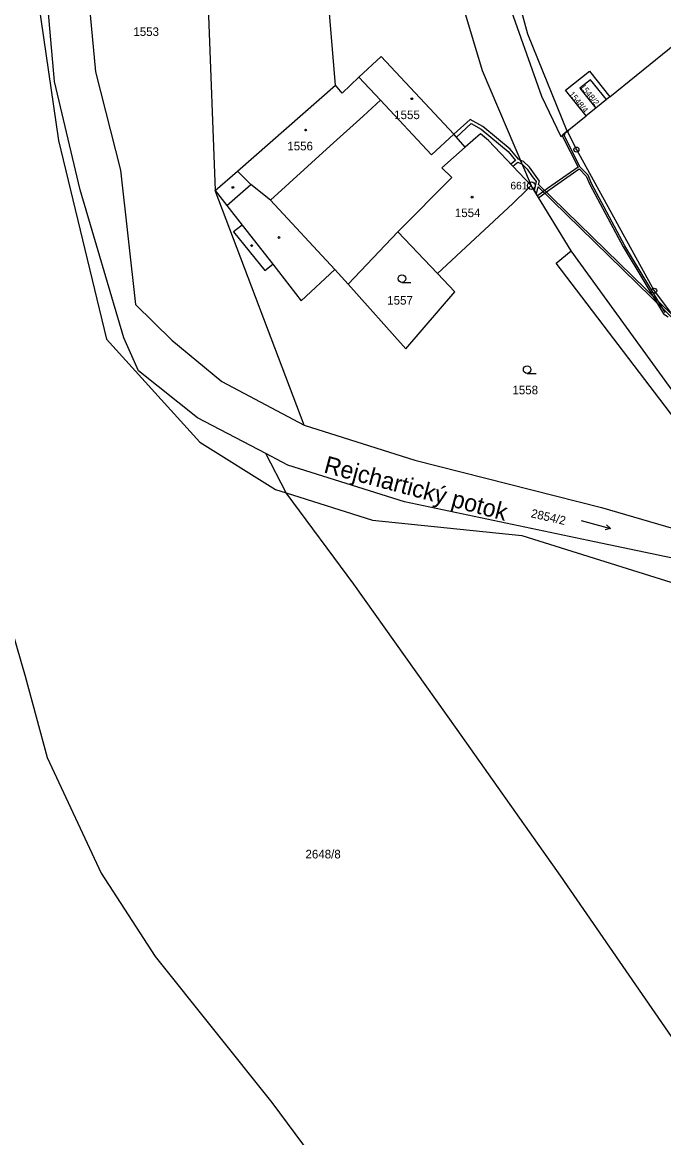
# Model space of a CAD drawing. Extents: x -562167 to -556918, y -1077891 to -1070763.
# Drawn here: x -560295.1 to -560168.6, y -1075431.3 to -1075211 of the extents above; entities that cross this region are included whole.
import ezdxf

# ---------------------------------------------------------------- set-up
doc = ezdxf.new("R2010")
doc.units = 0
for name, color, linetype in [('Hranice parcel', 7, 'Continuous'), ('Parcelní čísla', 7, 'Continuous'), ('Pop  PČ popisy', 7, 'Continuous'), ('Vnitřní kresba', 7, 'Continuous'), ('Věcná břemena k části', 7, 'Continuous'), ('Značky bodu BP', 7, 'Continuous'), ('Značky budov', 7, 'Continuous'), ('Značky kultur', 7, 'Continuous')]:
    doc.layers.add(name, color=color, linetype=linetype)

msp = doc.modelspace()

# ---------------------------------------------------------------- linework, layer by layer
at = {"layer": 'Hranice parcel'}
for p, q in [((-560195.41, -1075213.39), (-560213.2, -1075148.43)), ((-560233.39, -1075223.45), (-560237.46, -1075173.67)), ((-560258.5, -1075208.05), (-560257.08, -1075244.24)), ((-560179.25, -1075225.71), (-560156.69, -1075207.44)), ((-560187.64, -1075232.51), (-560195.41, -1075213.39)), ((-560252.69, -1075240.39), (-560233.39, -1075223.45)), ((-560228.76, -1075221.87), (-560224.48, -1075226.43)), ((-560179.91, -1075226.25), (-560182.01, -1075227.95)), ((-560179.25, -1075225.71), (-560179.91, -1075226.25)), ((-560187.64, -1075232.51), (-560183.9, -1075229.48)), ((-560182.01, -1075227.95), (-560183.9, -1075229.48)), ((-560187.64, -1075232.51), (-560185.83, -1075236.16)), ((-560257.08, -1075244.24), (-560252.69, -1075240.39)), ((-560186.88, -1075256.18), (-560194.75, -1075243.27)), ((-560239.53, -1075290.55), (-560257.08, -1075244.24)), ((-560253.48, -1075252.39), (-560247.3, -1075260.02)), ((-560247.12, -1075296.18), (-560260.61, -1075289.1)), ((-560243.08, -1075303.96), (-560247.12, -1075296.18)), ((-560242.79, -1075298.45), (-560247.12, -1075296.18))]:
    msp.add_line(p, q, dxfattribs=at)
for points in [[(-560468.72, -1074981.28), (-560446.94, -1075005.24), (-560438.95, -1075016.91), (-560425.77, -1075038.67), (-560409.04, -1075068.96), (-560398.41, -1075088.55), (-560384.84, -1075113.41), (-560359.86, -1075158.18), (-560352.19, -1075171.57), (-560344.85, -1075189.04), (-560335.77, -1075208.9), (-560321.29, -1075251.14), (-560313.71, -1075276.41), (-560308.43, -1075290.81), (-560301.52, -1075316.46), (-560294.61, -1075340.14), (-560290.27, -1075356.18), (-560279.56, -1075379.07), (-560268.94, -1075395.49), (-560245.91, -1075424.32), (-560221.55, -1075457.21), (-560206.93, -1075476.56), (-560193.15, -1075492.44), (-560170.99, -1075515.93)], [(-560377.5, -1075001.63), (-560371.77, -1075022.43), (-560361.38, -1075042.53), (-560353.72, -1075060.11), (-560342.27, -1075079.82), (-560325.5, -1075114.4), (-560301.62, -1075166.88), (-560296.28, -1075178.83), (-560291.97, -1075207.26), (-560288.04, -1075234.38), (-560278.55, -1075273.6), (-560260.14, -1075293.96), (-560245.2, -1075303.29), (-560243.08, -1075303.96)], [(-560213.2, -1075148.43), (-560209.41, -1075171.84), (-560199.73, -1075205.64), (-560192.7, -1075225.61)], [(-560284.98, -1075174.75), (-560283.71, -1075188.4), (-560280.69, -1075220.82), (-560275.79, -1075240.25), (-560272.84, -1075266.73), (-560265.66, -1075273.78), (-560255.76, -1075281.97), (-560239.53, -1075290.55)], [(-560260.61, -1075289.1), (-560272.24, -1075279.86), (-560275.15, -1075273.34), (-560283.73, -1075244.13), (-560288.79, -1075222.69), (-560292.95, -1075175.49)], [(-560215.2, -1075184.5), (-560204.42, -1075220.53), (-560194.75, -1075243.27)], [(-560210.04, -1075233.08), (-560224.35, -1075217.75), (-560228.76, -1075221.87)], [(-560183.9, -1075229.48), (-560187.96, -1075224.44), (-560183.23, -1075220.68), (-560179.25, -1075225.71)], [(-560228.76, -1075221.87), (-560232.04, -1075224.99), (-560233.39, -1075223.45)], [(-560179.91, -1075226.25), (-560183.06, -1075222.36), (-560185.16, -1075224.06), (-560182.01, -1075227.95)], [(-560192.7, -1075225.61), (-560188.93, -1075233.56), (-560187.64, -1075232.51)], [(-560224.48, -1075226.43), (-560227.9, -1075229.54), (-560234.39, -1075235.43), (-560246.19, -1075246.15)], [(-560210.04, -1075233.08), (-560214.42, -1075237.16), (-560224.48, -1075226.43)], [(-560194.75, -1075243.27), (-560203.15, -1075234.38), (-560204.74, -1075233.03), (-560207.76, -1075235.7), (-560210.04, -1075233.08)], [(-560185.83, -1075236.16), (-560170.49, -1075264.02), (-560167.24, -1075268.32)], [(-560246.19, -1075246.15), (-560250.07, -1075243.04), (-560252.69, -1075240.39)], [(-560213.26, -1075260.63), (-560198.37, -1075246.77), (-560195.48, -1075243.98), (-560194.75, -1075243.27)], [(-560257.08, -1075244.24), (-560254.79, -1075247.19), (-560251.77, -1075251.05), (-560253.48, -1075252.39)], [(-560230.88, -1075262.76), (-560221.04, -1075252.4), (-560213.26, -1075260.63)], [(-560142.4, -1075321.68), (-560151.85, -1075308.44), (-560189.85, -1075258.59), (-560186.88, -1075256.18)], [(-560131.73, -1075330.69), (-560140.28, -1075319.37), (-560149.99, -1075307.09), (-560186.88, -1075256.18)], [(-560247.3, -1075260.02), (-560245.73, -1075258.79), (-560240.11, -1075266)], [(-560240.11, -1075266), (-560233.49, -1075259.85), (-560230.88, -1075262.76)], [(-560230.88, -1075262.76), (-560219.49, -1075275.51), (-560209.84, -1075264.25), (-560213.26, -1075260.63)], [(-560239.53, -1075290.55), (-560217.71, -1075297.51), (-560180.89, -1075306.83), (-560163.49, -1075311.91), (-560151.81, -1075316.39), (-560142.4, -1075321.68)], [(-560045.55, -1075464.21), (-560067.84, -1075432.85), (-560097.73, -1075390.37), (-560116.01, -1075366.17), (-560124.2, -1075350.88), (-560131.1, -1075341.27), (-560136.59, -1075335.08), (-560145.89, -1075327.2), (-560154.9, -1075321.85), (-560165.27, -1075317.15), (-560182.25, -1075313.6), (-560219.76, -1075305.74), (-560242.79, -1075298.45)], [(-560126.48, -1075471.4), (-560152.86, -1075430.65), (-560165.73, -1075413.17), (-560188.91, -1075379.61), (-560209.38, -1075350.65), (-560229.71, -1075321.98), (-560243.08, -1075303.96)], [(-560243.08, -1075303.96), (-560226.06, -1075309.33), (-560196.59, -1075312.36), (-560154.01, -1075325.75)]]:
    msp.add_lwpolyline(points, dxfattribs=at)
at = {"layer": 'Vnitřní kresba'}
for p, q in [((-560212.37, -1075239.76), (-560207.76, -1075235.7)), ((-560212.37, -1075239.76), (-560210.42, -1075241.7)), ((-560254.79, -1075247.19), (-560250.07, -1075243.04)), ((-560221.04, -1075252.4), (-560210.42, -1075241.7)), ((-560246.19, -1075246.15), (-560233.49, -1075259.85)), ((-560251.77, -1075251.05), (-560245.73, -1075258.79))]:
    msp.add_line(p, q, dxfattribs=at)
at = {"layer": 'Věcná břemena k části'}
for points in [[(-560210.04, -1075233.08), (-560209.48, -1075233.72), (-560206.6, -1075231.03), (-560204.63, -1075232.1), (-560199.32, -1075236.52), (-560197.86, -1075238.28), (-560198.76, -1075239.02), (-560198.35, -1075239.46), (-560197.38, -1075238.66), (-560196.55, -1075239.04), (-560196.9, -1075238.22), (-560197.25, -1075238.07), (-560198.9, -1075236.1), (-560204.29, -1075231.6), (-560206.82, -1075230.23)], [(-560187.98, -1075232.79), (-560187.59, -1075232.6), (-560187.64, -1075232.51)], [(-560187.64, -1075232.51), (-560187.59, -1075232.6), (-560187.34, -1075232.48), (-560187.42, -1075232.33)], [(-560194.55, -1075241.46), (-560193.79, -1075242.44), (-560194.15, -1075244.25), (-560193.79, -1075244.85), (-560193.62, -1075244.64), (-560193.4, -1075243.52), (-560165.5, -1075270.76), (-560166.81, -1075268.92), (-560193.3, -1075243.06), (-560193.09, -1075242.37), (-560195.07, -1075239.64), (-560196.26, -1075238.49), (-560196.9, -1075238.22), (-560196.55, -1075239.04), (-560195.53, -1075240.03)]]:
    msp.add_lwpolyline(points, close=True, dxfattribs=at)
msp.add_lwpolyline([(-560168.32, -1075268.32), (-560176.28, -1075255.18), (-560182.85, -1075242.84), (-560183.54, -1075241.21), (-560185.06, -1075239.6), (-560188.15, -1075233.49), (-560188.05, -1075232.85), (-560188.52, -1075233.22), (-560188.57, -1075233.55), (-560185.49, -1075239.66), (-560191.51, -1075243.86), (-560193.5, -1075245.32), (-560193.29, -1075245.66), (-560191.27, -1075244.18), (-560185.26, -1075239.98), (-560183.88, -1075241.43), (-560183.21, -1075243.02), (-560176.62, -1075255.38), (-560168.62, -1075268.62), (-560167.72, -1075269.15)], dxfattribs=at)
at = {"layer": 'Značky bodu BP'}
for centre, radius in [((-560185.83, -1075236.16), 0.5), ((-560185.83, -1075236.16), 0.0303), ((-560194.75, -1075243.27), 0.75), ((-560194.75, -1075243.27), 0.03), ((-560170.49, -1075264.02), 0.5), ((-560170.49, -1075264.02), 0.0303)]:
    msp.add_circle(centre, radius, dxfattribs=at)
at = {"layer": 'Značky budov'}
for centre in [(-560218.31, -1075226.12), (-560239.25, -1075232.3), (-560253.6, -1075243.63), (-560206.41, -1075245.55), (-560244.5, -1075253.52), (-560249.9, -1075255.11)]:
    msp.add_circle(centre, 0.175, dxfattribs=at)
at = {"layer": 'Značky kultur'}
for p, q in [((-560220.26, -1075262.37), (-560218.51, -1075262.37)), ((-560195.55, -1075280.35), (-560193.8, -1075280.35)), ((-560184.87, -1075309.43), (-560179.08, -1075310.98)), ((-560179.08, -1075310.98), (-560180.15, -1075311.21)), ((-560179.08, -1075310.98), (-560179.89, -1075310.24))]:
    msp.add_line(p, q, dxfattribs=at)
for centre in [(-560220.26, -1075261.62), (-560195.55, -1075279.6)]:
    msp.add_circle(centre, 0.75, dxfattribs=at)

# ---------------------------------------------------------------- texts
at = {"layer": 'Parcelní čísla'}
for s, p in [('1553', (-560273.24, -1075213.72)), ('1555', (-560221.78, -1075230.14)), ('1556', (-560242.87, -1075236.31)), ('1554', (-560209.81, -1075249.49)), ('1557', (-560223.15, -1075266.77)), ('1558', (-560198.45, -1075284.48)), ('2648/8', (-560239.28, -1075376.13))]:
    msp.add_text(s, height=1.7, dxfattribs=at).set_placement(p)
for s, height, rotation, p in [('1548/2', 1.19, 309, (-560185.21, -1075223.79)), ('1548/4', 1.19, 309, (-560187.38, -1075225.25)), ('2854/2', 1.7, 347, (-560194.92, -1075308.74))]:
    msp.add_text(s, height=height, rotation=rotation, dxfattribs=at).set_placement(p)
at = {"layer": 'Pop  PČ popisy'}
msp.add_text('Rejchartický potok', height=3.4, rotation=345, dxfattribs=at).set_placement((-560235.85, -1075299.87))
at = {"layer": 'Značky bodu BP'}
msp.add_text('661', height=1.5, dxfattribs=at).set_placement((-560198.85, -1075244.02))

doc.saveas('drawing.dxf')
